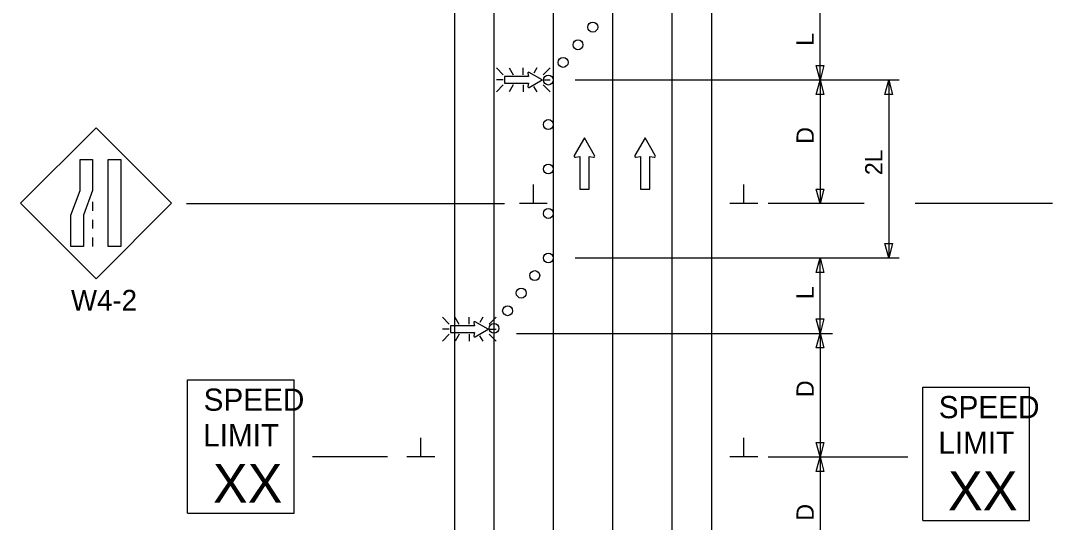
# Model space of a CAD drawing. Extents: x 16503 to 19508, y 5728 to 6974.
# Drawn here: x 17770 to 18187.7, y 6467.2 to 6670.3 of the extents above; entities that cross this region are included whole.
import ezdxf

# ---------------------------------------------------------------- set-up
doc = ezdxf.new("R2010")
doc.units = 0
for name, color, linetype in [('ALI_LEGAL_EX', 7, 'Continuous'), ('MT_SCRATCH_LEVEL_E', 7, 'Continuous'), ('PAVT_EDGE_EX', 7, 'Continuous'), ('TRAFFIC_SIGNS_PR', 7, 'Continuous'), ('TYPICAL_TEXT_DIMEN_PR', 7, 'Continuous')]:
    doc.layers.add(name, color=color, linetype=linetype)

msp = doc.modelspace()

# ---------------------------------------------------------------- linework, layer by layer
at = {"layer": 'ALI_LEGAL_EX'}
for p, q in [((17985.63, 6921.33), (17985.63, 6077.19)), ((18009.63, 6921.33), (18009.63, 6077.19))]:
    msp.add_line(p, q, dxfattribs=at)
for points in [[(17985.63, 6621.33), (17985.63, 6596.33)], [(18009.63, 6621.33), (18009.63, 6596.33)], [(17985.63, 6521.33), (17985.63, 6496.33)], [(18009.63, 6521.33), (18009.63, 6496.33)]]:
    msp.add_lwpolyline(points, dxfattribs=at)
at = {"layer": 'MT_SCRATCH_LEVEL_E'}
for p, q in [((17998.21, 6622.84), (17994.1, 6615.6)), ((18002.35, 6615.6), (17998.21, 6622.84)), ((18022.77, 6622.84), (18018.65, 6615.6)), ((18026.91, 6615.6), (18022.77, 6622.84)), ((17994.58, 6614.92), (17996.35, 6615.24)), ((17996.35, 6615.24), (17996.35, 6601.98)), ((18000.1, 6601.98), (18000.1, 6615.24)), ((18000.1, 6615.24), (18001.87, 6614.92)), ((18019.14, 6614.92), (18020.91, 6615.24)), ((18020.91, 6615.24), (18020.91, 6601.98)), ((18024.66, 6601.98), (18024.66, 6615.24)), ((18024.66, 6615.24), (18026.43, 6614.92)), ((17996.35, 6601.98), (18000.1, 6601.98)), ((18020.91, 6601.98), (18024.66, 6601.98))]:
    msp.add_line(p, q, dxfattribs=at)
for centre, start, end in [((17994.5, 6615.38), 150.4248, 279.9638), ((18001.94, 6615.38), 260.0362, 29.7731), ((18019.06, 6615.38), 150.4248, 279.9638), ((18026.5, 6615.38), 260.0362, 29.7731)]:
    msp.add_arc(centre, 0.463, start, end, dxfattribs=at)
at = {"layer": 'PAVT_EDGE_EX'}
for p, q in [((17945.63, 6921.33), (17945.63, 5988.51)), ((17961.63, 6921.33), (17961.63, 5988.51)), ((18033.63, 6921.33), (18033.63, 5988.51)), ((18049.63, 6921.33), (18049.63, 5988.51))]:
    msp.add_line(p, q, dxfattribs=at)
at = {"layer": 'TRAFFIC_SIGNS_PR'}
for p, q in [((17965.41, 6648.3), (17962.59, 6651.12)), ((17967.71, 6651.12), (17969.33, 6648.3)), ((17973.49, 6648.3), (17973.49, 6651.12)), ((17978.96, 6651.12), (17977.76, 6649.02)), ((17984.4, 6651.11), (17981.58, 6648.3)), ((17965.41, 6646.27), (17962.59, 6646.27)), ((17981.58, 6646.27), (17984.4, 6646.27)), ((17965.41, 6644.23), (17962.59, 6641.41)), ((17969.36, 6644.23), (17967.73, 6641.41)), ((17973.49, 6644.23), (17973.49, 6641.41)), ((17977.68, 6643.6), (17978.94, 6641.41)), ((17984.4, 6641.41), (17981.58, 6644.23)), ((17800.55, 6626.87), (17770.01, 6596.32)), ((17831.1, 6596.32), (17800.55, 6626.87)), ((17770.01, 6596.32), (17800.55, 6565.77)), ((17799.15, 6596.87), (17799.15, 6593.27)), ((17800.55, 6565.77), (17831.1, 6596.32)), ((17799.15, 6589.67), (17799.15, 6586.07)), ((17799.15, 6582.47), (17799.15, 6578.87)), ((17943.54, 6547.35), (17940.72, 6550.17)), ((17945.83, 6550.16), (17947.46, 6547.35)), ((17951.62, 6547.35), (17951.62, 6550.16)), ((17957.09, 6550.16), (17955.88, 6548.07)), ((17962.53, 6550.16), (17959.71, 6547.35)), ((17943.54, 6545.31), (17940.72, 6545.31)), ((17959.71, 6545.31), (17962.53, 6545.31)), ((17943.54, 6543.28), (17940.72, 6540.46)), ((17947.49, 6543.28), (17945.86, 6540.46)), ((17951.62, 6543.28), (17951.62, 6540.46)), ((17955.8, 6542.65), (17957.06, 6540.46)), ((17962.53, 6540.46), (17959.71, 6543.28)), ((17837.58, 6524.84), (17880.78, 6524.84)), ((17837.58, 6470.84), (17837.58, 6524.84)), ((17880.78, 6470.84), (17880.78, 6524.84)), ((18135.18, 6521.84), (18178.38, 6521.84)), ((18135.18, 6467.84), (18135.18, 6521.84)), ((18178.38, 6467.84), (18178.38, 6521.84)), ((17837.58, 6470.84), (17880.78, 6470.84)), ((18135.18, 6467.84), (18178.38, 6467.84))]:
    msp.add_line(p, q, dxfattribs=at)
for points in [[(17975.82, 6643.25), (17981.13, 6646.27), (17975.82, 6649.31)], [(17975.32, 6648.95), (17975.55, 6647.65), (17965.83, 6647.65), (17965.83, 6644.91), (17975.55, 6644.91), (17975.32, 6643.6)], [(17953.45, 6547.99), (17953.68, 6546.7), (17943.96, 6546.7), (17943.96, 6543.95), (17953.68, 6543.95), (17953.45, 6542.65)], [(17953.95, 6542.3), (17959.26, 6545.31), (17953.95, 6548.35)]]:
    msp.add_lwpolyline(points, dxfattribs=at)
for points in [[(17799.15, 6614.02), (17799.15, 6601.44), (17795.39, 6591.45), (17795.39, 6578.87), (17790.33, 6578.87), (17790.33, 6591.45), (17794.1, 6601.44), (17794.1, 6614.02)], [(17810.55, 6614.02), (17810.55, 6578.87), (17805.5, 6578.87), (17805.5, 6614.02)]]:
    msp.add_lwpolyline(points, close=True, dxfattribs=at)
for centre in [(18001.63, 6667.62), (17995.63, 6660.48), (17989.63, 6653.34), (17983.63, 6646.2), (17983.63, 6628.19), (17983.63, 6610.19), (17983.63, 6592.19), (17983.63, 6574.19), (17978.14, 6567.06), (17972.64, 6559.94), (17967.14, 6552.81), (17961.64, 6545.68)]:
    msp.add_circle(centre, 2, dxfattribs=at)
for centre, start, end in [((17975.66, 6649.01), 61.4833, 189.9593), ((17975.66, 6643.55), 170.7308, 298.8916), ((17953.78, 6548.05), 61.4833, 189.9593), ((17953.78, 6542.6), 170.7308, 298.8916)]:
    msp.add_arc(centre, 0.341, start, end, dxfattribs=at)
at = {"layer": 'TYPICAL_TEXT_DIMEN_PR'}
for p, q in [((18093.63, 6646.19), (18093.63, 6676.76)), ((18093.63, 6646.19), (18092.06, 6652.06)), ((18092.06, 6652.06), (18093.63, 6652.06)), ((18093.63, 6652.06), (18095.2, 6652.06)), ((18095.2, 6652.06), (18093.63, 6646.19)), ((18125.68, 6646.19), (17994.53, 6646.19)), ((18092.06, 6640.33), (18093.63, 6646.19)), ((18093.63, 6646.19), (18093.63, 6596.19)), ((18093.63, 6646.19), (18095.2, 6640.33)), ((18119.87, 6640.33), (18121.44, 6646.19)), ((18121.44, 6646.19), (18123.01, 6640.33)), ((18121.44, 6646.19), (18121.44, 6574.19)), ((18093.63, 6640.33), (18092.06, 6640.33)), ((18095.2, 6640.33), (18093.63, 6640.33)), ((18121.44, 6640.33), (18119.87, 6640.33)), ((18123.01, 6640.33), (18121.44, 6640.33)), ((17977.56, 6596.19), (17977.56, 6603.98)), ((18062.76, 6596.19), (18062.76, 6603.98)), ((18093.63, 6596.19), (18092.06, 6602.06)), ((18092.06, 6602.06), (18093.63, 6602.06)), ((18093.63, 6602.06), (18095.2, 6602.06)), ((18095.2, 6602.06), (18093.63, 6596.19)), ((18121.44, 6601.06), (18121.44, 6597.3)), ((17837.17, 6596.19), (17965.83, 6596.19)), ((17983.19, 6596.19), (17971.94, 6596.19)), ((18068.38, 6596.19), (18057.13, 6596.19)), ((18111.49, 6596.19), (18072.63, 6596.19)), ((18187.67, 6596.19), (18132.19, 6596.19)), ((18121.44, 6574.19), (18119.87, 6580.06)), ((18119.87, 6580.06), (18121.44, 6580.06)), ((18121.44, 6580.06), (18123.01, 6580.06)), ((18123.01, 6580.06), (18121.44, 6574.19)), ((17994.53, 6574.19), (18125.68, 6574.19)), ((18092.06, 6568.33), (18093.63, 6574.19)), ((18093.63, 6543.63), (18093.63, 6574.19)), ((18093.63, 6574.19), (18095.2, 6568.33)), ((18093.63, 6568.33), (18092.06, 6568.33)), ((18095.2, 6568.33), (18093.63, 6568.33)), ((18093.63, 6543.63), (18092.06, 6549.49)), ((18092.06, 6549.49), (18093.63, 6549.49)), ((18093.63, 6549.49), (18095.2, 6549.49)), ((18095.2, 6549.49), (18093.63, 6543.63)), ((17970.8, 6543.63), (18098.63, 6543.63)), ((18092.06, 6537.77), (18093.63, 6543.63)), ((18093.63, 6543.63), (18093.63, 6493.63)), ((18093.63, 6543.63), (18095.2, 6537.77)), ((18093.63, 6537.77), (18092.06, 6537.77)), ((18095.2, 6537.77), (18093.63, 6537.77)), ((17932.02, 6493.63), (17932.02, 6501.41)), ((18062.76, 6493.63), (18062.76, 6501.41)), ((18093.63, 6493.63), (18092.06, 6499.49)), ((18092.06, 6499.49), (18093.63, 6499.49)), ((18093.63, 6499.49), (18095.2, 6499.49)), ((18095.2, 6499.49), (18093.63, 6493.63)), ((17918.58, 6493.63), (17888.17, 6493.63)), ((17937.64, 6493.63), (17926.39, 6493.63)), ((18068.38, 6493.63), (18057.13, 6493.63)), ((18072.63, 6493.63), (18129.14, 6493.63)), ((18092.06, 6487.77), (18093.63, 6493.63)), ((18093.63, 6493.63), (18093.63, 6443.63)), ((18093.63, 6493.63), (18095.2, 6487.77)), ((18093.63, 6487.77), (18092.06, 6487.77)), ((18095.2, 6487.77), (18093.63, 6487.77))]:
    msp.add_line(p, q, dxfattribs=at)

# ---------------------------------------------------------------- texts
at = {"layer": 'TRAFFIC_SIGNS_PR'}
for s, height, p in [('W4-2', 8.37, (17790.38, 6552.9)), ('SPEED', 9, (17844.07, 6512.31)), ('SPEED', 9, (18141.67, 6509.31)), ('LIMIT', 9, (17843.89, 6497.91)), ('LIMIT', 9, (18141.49, 6494.91)), ('XX', 15.785, (17847.84, 6475.06)), ('XX', 15.785, (18145.43, 6472.07))]:
    msp.add_text(s, height=height, dxfattribs=at).set_placement(p)
at = {"layer": 'TYPICAL_TEXT_DIMEN_PR'}
for s, p in [('L', (18091.08, 6660.05)), ('D', (18091.08, 6620.41)), ('2L', (18118.88, 6607.7)), ('L', (18091.08, 6557.49)), ('D', (18091.08, 6517.85)), ('D', (18091.08, 6467.85))]:
    msp.add_text(s, height=7, rotation=90, dxfattribs=at).set_placement(p)

doc.saveas('drawing.dxf')
